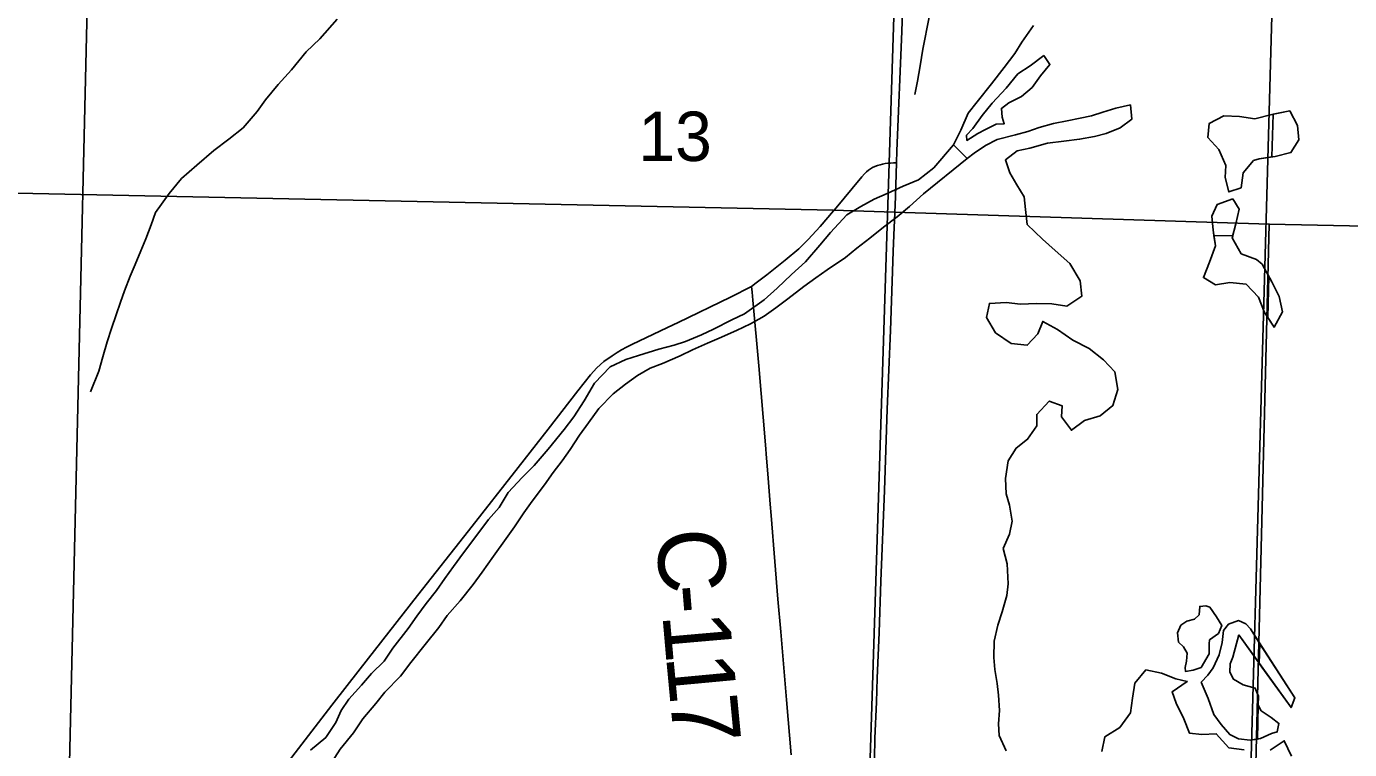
# Model space of a CAD drawing. Extents: x -38.1 to 35.9, y -2.7 to 28.5.
# Drawn here: x 20.979 to 22.099, y 18.084 to 18.696 of the extents above; entities that cross this region are included whole.
import ezdxf

# ---------------------------------------------------------------- set-up
doc = ezdxf.new("R2010")
doc.units = 0
for name, color, linetype in [('GM_X_City_Street_Text', 7, 'Continuous'), ('GM_X_Corporation', 7, 'Continuous'), ('GM_X_Interchange_Ramps', 7, 'Continuous'), ('GM_X_Interstate_Shield', 7, 'Continuous'), ('GM_X_Major_River', 7, 'Continuous'), ('GM_X_Minor_River', 7, 'Continuous'), ('GM_X_Section', 7, 'Continuous'), ('GM_X_Township', 7, 'Continuous'), ('GM_X_US_Route', 7, 'Continuous')]:
    doc.layers.add(name, color=color, linetype=linetype)

msp = doc.modelspace()

# ---------------------------------------------------------------- linework, layer by layer
at = {"layer": 'GM_X_City_Street_Text'}
for points in [[(21.6623, 18.5402), (21.663, 18.541), (21.6863, 18.569), (21.6884, 18.5713), (21.6902, 18.5731), (21.692, 18.5745), (21.6936, 18.5756), (21.6954, 18.5767), (21.6973, 18.5776), (21.6996, 18.5785), (21.7019, 18.5792), (21.7038, 18.5797), (21.706, 18.5801), (21.7082, 18.5804), (21.7105, 18.5806), (21.713, 18.5808), (21.7156, 18.5808)], [(21.5928, 18.476), (21.5968, 18.4791), (21.6058, 18.4858), (21.6214, 18.4982), (21.6328, 18.508), (21.6409, 18.5157), (21.6511, 18.5267), (21.6623, 18.5402)], [(21.5217, 18.4412), (21.5308, 18.4456), (21.575, 18.467), (21.5928, 18.476)], [(21.6056, 18.3306), (21.6046, 18.3419), (21.599, 18.4088), (21.5941, 18.4645), (21.5935, 18.4713), (21.5928, 18.476)], [(21.1781, 18.0447), (21.1847, 18.0529), (21.2178, 18.0958), (21.2376, 18.1213), (21.2615, 18.1522), (21.3101, 18.2144), (21.3532, 18.2691), (21.3954, 18.3228), (21.4206, 18.3552), (21.4457, 18.3876), (21.4565, 18.4012), (21.462, 18.4071), (21.4679, 18.4124), (21.4749, 18.4174), (21.4791, 18.42), (21.4828, 18.4223), (21.4871, 18.4246), (21.4915, 18.4269), (21.5217, 18.4412)], [(21.6087, 18.2917), (21.6067, 18.3172), (21.6056, 18.3306)], [(21.6127, 18.2431), (21.6095, 18.2819), (21.6087, 18.2917)], [(21.6264, 18.0794), (21.6226, 18.1259), (21.6178, 18.1834), (21.6152, 18.2113), (21.6127, 18.2431)]]:
    msp.add_lwpolyline(points, dxfattribs=at)
at = {"layer": 'GM_X_Corporation'}
msp.add_lwpolyline([(25.4101, 13.4873), (25.0847, 13.9186), (24.5478, 14.5412), (23.9622, 15.2897), (23.3945, 15.9977), (22.8429, 16.6968), (22.7771, 16.7664), (22.2793, 17.0387), (22.174, 17.095), (22.1183, 17.1348), (22.0806, 17.1798), (21.9636, 17.4041), (21.7841, 17.7749), (21.744, 17.8537), (21.7155, 17.9287), (21.6978, 17.9866), (21.6921, 18.0413), (21.6956, 18.1468), (21.7163, 18.7934), (21.7602, 19.7303), (21.7602, 19.7308)], dxfattribs=at)
at = {"layer": 'GM_X_Interchange_Ramps'}
msp.add_line((21.7134, 18.5196), (21.7141, 18.5385), dxfattribs=at)
for points in [[(21.7156, 18.5808), (21.7159, 18.5908), (21.72, 18.692), (21.7218, 18.7436), (21.7237, 18.7933)], [(21.7141, 18.5385), (21.7147, 18.5523), (21.7156, 18.5808)], [(21.6969, 18.076), (21.6974, 18.0934), (21.6986, 18.1238), (21.6993, 18.1443), (21.7008, 18.1828), (21.7023, 18.2263), (21.7054, 18.3032), (21.7078, 18.3722), (21.7104, 18.4386), (21.7129, 18.5057), (21.7134, 18.5196)]]:
    msp.add_lwpolyline(points, dxfattribs=at)
at = {"layer": 'GM_X_Interstate_Shield'}
for p, q in [((22.0335, 18.5857), (22.0345, 18.6219)), ((21.764, 18.5961), (21.7753, 18.5843)), ((22.0003, 18.5189), (21.9844, 18.5193)), ((22.03, 18.4497), (22.0309, 18.4845)), ((22.0228, 18.1567), (22.0233, 18.1734)), ((22.0228, 18.1567), (22.0233, 18.1734)), ((22.0219, 18.1214), (22.0221, 18.129)), ((22.0219, 18.1214), (22.0212, 18.0927))]:
    msp.add_line(p, q, dxfattribs=at)
for points in [[(21.8317, 18.6971), (21.8217, 18.683), (21.8158, 18.6733), (21.8067, 18.6614), (21.796, 18.6476), (21.7838, 18.6324), (21.7763, 18.6228), (21.7702, 18.6085), (21.764, 18.5961)], [(21.8404, 18.6718), (21.8288, 18.663), (21.8183, 18.6561), (21.8084, 18.6439), (21.7967, 18.6313), (21.788, 18.6209), (21.7801, 18.6098), (21.775, 18.6042), (21.7752, 18.5997), (21.7845, 18.6055), (21.7909, 18.609)], [(21.7909, 18.609), (21.7999, 18.6134), (21.8068, 18.6139), (21.805, 18.6193), (21.8045, 18.6269), (21.8107, 18.6317), (21.8215, 18.637), (21.8305, 18.6447), (21.8376, 18.6544), (21.8455, 18.664), (21.8404, 18.6718)], [(21.7753, 18.5843), (21.7814, 18.5889), (21.791, 18.5954), (21.8007, 18.6004), (21.8164, 18.6045), (21.8267, 18.6073), (21.8363, 18.6108), (21.8486, 18.6142), (21.86, 18.6162), (21.8711, 18.6185), (21.8807, 18.6205), (21.8903, 18.6237), (21.9014, 18.6271), (21.9136, 18.6298), (21.9148, 18.6177), (21.9051, 18.6103), (21.8931, 18.6057), (21.8832, 18.603), (21.8706, 18.6007), (21.8572, 18.5992), (21.8435, 18.5973), (21.8286, 18.5932)], [(22.0345, 18.6219), (22.0189, 18.6181), (22.006, 18.62), (21.9927, 18.6207), (21.9804, 18.6142), (21.9793, 18.6021), (21.9885, 18.592), (21.9945, 18.5785), (21.9938, 18.5683), (21.9969, 18.5561), (22.0073, 18.5596), (22.0092, 18.5724), (22.0178, 18.5828)], [(22.0323, 18.6215), (22.0189, 18.6181), (22.006, 18.62), (21.9927, 18.6207), (21.9804, 18.6142), (21.9793, 18.6021), (21.9885, 18.592), (21.9945, 18.5785), (21.9938, 18.5683), (21.9969, 18.5561), (22.0073, 18.5596), (22.0092, 18.5724), (22.0178, 18.5828)], [(22.0178, 18.5828), (22.0228, 18.5842), (22.0361, 18.5861), (22.0495, 18.5895), (22.0563, 18.6003), (22.0552, 18.6125), (22.0487, 18.6248)], [(22.0323, 18.6215), (22.0487, 18.6248)], [(22.0487, 18.6248), (22.0552, 18.6125), (22.0563, 18.6003), (22.0495, 18.5895), (22.0361, 18.5861), (22.0335, 18.5857)], [(22.0345, 18.6219), (22.0487, 18.6248)], [(21.8286, 18.5932), (21.8179, 18.5908), (21.8078, 18.5832), (21.8116, 18.5724), (21.8174, 18.562), (21.8236, 18.552), (21.8248, 18.5413), (21.8263, 18.5284), (21.8392, 18.5162), (21.8499, 18.5064), (21.8625, 18.4954), (21.8712, 18.4808), (21.8724, 18.4678), (21.8599, 18.4594), (21.8471, 18.4613), (21.8342, 18.4617), (21.8205, 18.461), (21.8084, 18.4625), (21.7943, 18.4617), (21.7917, 18.4497), (21.7993, 18.4369), (21.8127, 18.4278), (21.8263, 18.4263), (21.8353, 18.4359), (21.8394, 18.4464), (21.8518, 18.4396), (21.8648, 18.4305), (21.8786, 18.4236), (21.8909, 18.4138), (21.9005, 18.4036), (21.9031, 18.3888), (21.8989, 18.3752), (21.888, 18.3664), (21.8749, 18.3626), (21.8637, 18.3542), (21.8553, 18.3655), (21.8559, 18.3749), (21.845, 18.379), (21.8344, 18.3676), (21.8345, 18.3581), (21.8266, 18.3466), (21.8169, 18.3392), (21.8101, 18.3284), (21.8078, 18.3133), (21.8085, 18.3004), (21.8113, 18.2908), (21.8135, 18.2771), (21.8113, 18.2662), (21.806, 18.2542), (21.8094, 18.2412), (21.8101, 18.2241), (21.809, 18.2142), (21.8052, 18.2003), (21.8014, 18.189), (21.7984, 18.1755), (21.798, 18.1618), (21.7988, 18.1515), (21.8007, 18.1397), (21.8019, 18.1298), (21.8027, 18.1169), (21.802, 18.1055), (21.8025, 18.0956), (21.8085, 18.0826)], [(22.0178, 18.5828), (22.0228, 18.5842), (22.0335, 18.5857)], [(22.0004, 18.5503), (21.9871, 18.5454), (21.9826, 18.5356), (21.9838, 18.5238), (21.9857, 18.5105), (21.9807, 18.4966), (21.9754, 18.4835), (21.9858, 18.4775), (21.9977, 18.4794), (22.0117, 18.4779), (22.022, 18.4669), (22.0273, 18.4539), (22.0353, 18.4415), (22.0425, 18.4546), (22.0395, 18.4676), (22.0334, 18.4799), (22.0251, 18.4949)], [(22.0004, 18.5503), (21.9871, 18.5454), (21.9826, 18.5356), (21.9838, 18.5238), (21.9844, 18.5193)], [(22.0251, 18.4949), (22.0203, 18.4989), (22.0075, 18.5038), (21.9999, 18.5173), (22.0029, 18.529), (22.0056, 18.5414)], [(22.0003, 18.5189), (22.0029, 18.529), (22.0056, 18.5414)], [(22.0056, 18.5414), (22.0004, 18.5503)], [(21.9844, 18.5193), (21.9857, 18.5105), (21.9807, 18.4966), (21.9754, 18.4835), (21.9858, 18.4775), (21.9977, 18.4794), (22.0117, 18.4779), (22.022, 18.4669), (22.0273, 18.4539), (22.03, 18.4497)], [(22.0251, 18.4949), (22.0203, 18.4989), (22.0075, 18.5038), (21.9999, 18.5173), (22.0003, 18.5189)], [(22.0309, 18.4845), (22.0251, 18.4949)], [(22.0309, 18.4845), (22.0334, 18.4799), (22.0395, 18.4676), (22.0425, 18.4546), (22.0353, 18.4415), (22.03, 18.4497)], [(21.9866, 18.1962), (21.9808, 18.2044), (21.9774, 18.2056), (21.9724, 18.205), (21.9718, 18.1978), (21.9679, 18.1941), (21.9614, 18.1924), (21.9564, 18.1891), (21.9535, 18.1827), (21.9545, 18.1748), (21.9585, 18.1708), (21.9618, 18.1654), (21.9612, 18.1586), (21.9599, 18.1533), (21.9602, 18.1499), (21.9667, 18.1509), (21.9736, 18.1533)], [(21.9736, 18.1533), (21.9804, 18.1649), (21.9802, 18.1733), (21.9807, 18.1767), (21.9881, 18.1821), (21.991, 18.1889), (21.9866, 18.1962)], [(22.0233, 18.1734), (22.0152, 18.1859), (22.0115, 18.1902), (22.0051, 18.193), (21.9967, 18.1899), (21.9924, 18.1847), (21.9913, 18.1745), (21.9887, 18.1639), (21.9838, 18.153), (21.9791, 18.1467), (21.9736, 18.1408)], [(22.0055, 18.1809), (22.0497, 18.1193), (22.053, 18.1275), (22.0152, 18.1859), (22.0115, 18.1902), (22.0051, 18.193), (21.9967, 18.1899), (21.9924, 18.1847), (21.9913, 18.1745), (21.9887, 18.1639), (21.9838, 18.153), (21.9791, 18.1467), (21.9736, 18.1408)], [(21.9736, 18.1408), (21.9796, 18.127), (21.9842, 18.1136), (21.9904, 18.105), (21.9977, 18.0965), (22.0052, 18.0928), (22.0151, 18.0918), (22.0238, 18.0931), (22.0331, 18.0974), (22.038, 18.0987), (22.0394, 18.1059), (22.0327, 18.111), (22.0245, 18.1166), (22.0216, 18.122), (22.0222, 18.1288), (22.0194, 18.1357), (22.0092, 18.1386), (22.001, 18.1434), (21.9978, 18.1492), (21.998, 18.1564), (22.0004, 18.162), (22.0055, 18.1809)], [(22.0221, 18.129), (22.0194, 18.1357), (22.0092, 18.1386), (22.001, 18.1434), (21.9978, 18.1492), (21.998, 18.1564), (22.0004, 18.162), (22.0055, 18.1809)], [(22.0055, 18.1809), (22.0225, 18.1572)], [(22.0233, 18.1734), (22.053, 18.1275), (22.0497, 18.1193), (22.0228, 18.1567)], [(21.8894, 18.0821), (21.8921, 18.0946), (21.9048, 18.1026), (21.9136, 18.1148), (21.9154, 18.1273), (21.9173, 18.1401), (21.9268, 18.1513), (21.94, 18.1486), (21.952, 18.1437), (21.9618, 18.1415), (21.949, 18.1328), (21.9525, 18.1232), (21.959, 18.1097), (21.9636, 18.0978), (21.9742, 18.0964), (21.9863, 18.0972), (21.997, 18.0851), (22.0099, 18.0836)], [(21.9736, 18.1408), (21.9796, 18.127), (21.9842, 18.1136), (21.9904, 18.105), (21.9977, 18.0965), (22.0052, 18.0928), (22.0151, 18.0918), (22.0212, 18.0927)], [(22.0212, 18.0927), (22.0238, 18.0931), (22.0331, 18.0974), (22.038, 18.0987), (22.0394, 18.1059), (22.0327, 18.111), (22.0245, 18.1166), (22.0219, 18.1214)], [(22.0319, 18.0833), (22.0439, 18.0913), (22.05, 18.0783)]]:
    msp.add_lwpolyline(points, dxfattribs=at)
at = {"layer": 'GM_X_Major_River'}
msp.add_line((21.7134, 18.5196), (21.7141, 18.5385), dxfattribs=at)
for points in [[(21.7156, 18.5808), (21.7159, 18.5908), (21.72, 18.692), (21.7218, 18.7436), (21.7237, 18.7933)], [(21.7141, 18.5385), (21.7147, 18.5523), (21.7156, 18.5808)], [(21.6969, 18.076), (21.6974, 18.0934), (21.6986, 18.1238), (21.6993, 18.1443), (21.7008, 18.1828), (21.7023, 18.2263), (21.7054, 18.3032), (21.7078, 18.3722), (21.7104, 18.4386), (21.7129, 18.5057), (21.7134, 18.5196)]]:
    msp.add_lwpolyline(points, dxfattribs=at)
at = {"layer": 'GM_X_Section'}
msp.add_line((21.7753, 18.5843), (21.764, 18.5961), dxfattribs=at)
for points in [[(21.2419, 18.7024), (21.2274, 18.6858), (21.2157, 18.6747), (21.2034, 18.6595), (21.1921, 18.647), (21.1814, 18.634), (21.1743, 18.6243), (21.1625, 18.6103)], [(21.7434, 18.7042), (21.738, 18.677), (21.7357, 18.663), (21.7334, 18.6498), (21.7312, 18.6385)], [(21.1625, 18.6103), (21.1504, 18.6007), (21.1376, 18.5912), (21.1232, 18.5788), (21.1103, 18.5674), (21.0997, 18.5548), (21.0882, 18.5388), (21.0845, 18.5283), (21.0799, 18.5163), (21.0758, 18.5061), (21.0709, 18.4945), (21.0668, 18.4848), (21.0619, 18.4724), (21.0586, 18.4626), (21.0549, 18.4521), (21.0511, 18.4405), (21.0474, 18.4292), (21.0436, 18.4164), (21.0402, 18.4043), (21.0332, 18.3867)], [(21.764, 18.5961), (21.7472, 18.5766), (21.7343, 18.5663), (21.7213, 18.561), (21.7078, 18.5549), (21.6966, 18.5499), (21.6854, 18.5438), (21.6735, 18.5366), (21.6597, 18.5218), (21.6507, 18.511), (21.6385, 18.497), (21.6268, 18.4863), (21.6146, 18.4745), (21.6037, 18.4646), (21.587, 18.4529), (21.5762, 18.4479), (21.5608, 18.44), (21.5504, 18.435), (21.537, 18.4293), (21.5274, 18.4262), (21.5144, 18.4228), (21.4971, 18.4176), (21.4864, 18.4141), (21.4733, 18.408), (21.4599, 18.394), (21.4511, 18.3791), (21.4424, 18.3657), (21.4341, 18.3549), (21.4207, 18.3382), (21.4089, 18.3245), (21.3987, 18.3142), (21.3869, 18.3016), (21.3793, 18.2889), (21.3703, 18.2786), (21.3628, 18.2689), (21.349, 18.2504), (21.3406, 18.2388), (21.3331, 18.2288), (21.326, 18.2184), (21.3173, 18.2076), (21.3094, 18.1969), (21.3022, 18.1864), (21.2892, 18.1698), (21.2817, 18.1586), (21.2711, 18.1483), (21.2625, 18.1383), (21.2518, 18.1264), (21.2455, 18.1168), (21.241, 18.1066), (21.2323, 18.094), (21.2194, 18.0834)], [(21.4001, 18.2842), (21.4072, 18.2942), (21.4175, 18.3079), (21.425, 18.3184), (21.4326, 18.3284), (21.4393, 18.338), (21.4472, 18.35), (21.4548, 18.3604), (21.4635, 18.3726), (21.4756, 18.3852), (21.4861, 18.3932), (21.4962, 18.4005), (21.507, 18.4067), (21.5174, 18.4109), (21.5324, 18.4173), (21.5428, 18.4223), (21.5555, 18.428), (21.5655, 18.4323), (21.5802, 18.4387), (21.5921, 18.4444), (21.6037, 18.4509), (21.6134, 18.4578), (21.6235, 18.4655), (21.6371, 18.4761), (21.6472, 18.4834), (21.6569, 18.49), (21.6724, 18.5005), (21.6821, 18.5086), (21.693, 18.517), (21.7047, 18.5262), (21.7163, 18.5349), (21.7265, 18.5438), (21.7386, 18.5544), (21.7753, 18.5843)], [(21.2374, 18.073), (21.2445, 18.0842), (21.2559, 18.0979), (21.2639, 18.1098), (21.2749, 18.1227), (21.2824, 18.1324), (21.2957, 18.146), (21.3044, 18.1575), (21.3166, 18.1727), (21.3281, 18.1872), (21.3352, 18.1973), (21.3462, 18.2098), (21.3573, 18.2236), (21.3648, 18.234), (21.3743, 18.2477), (21.385, 18.2626), (21.3921, 18.2723), (21.4001, 18.2842)]]:
    msp.add_lwpolyline(points, dxfattribs=at)
at = {"layer": 'GM_X_US_Route'}
for points in [[(20.0353, 19.0758), (21.0384, 19.0503), (21.0147, 18.0482), (20.0086, 18.0758)], [(21.0384, 19.0503), (22.0424, 19.0296), (22.0145, 18.0265), (21.0147, 18.0482)], [(23.1004, 19.0039), (23.0833, 18.0071), (22.0145, 18.0265), (22.0424, 19.0296)]]:
    msp.add_lwpolyline(points, close=True, dxfattribs=at)
for points in [[(21.9943, 17.03), (21.7582, 17.2984), (21.9963, 17.2757), (22.0014, 17.3284), (22.0312, 18.5289), (21.7139, 18.539), (21.6621, 18.5408), (20.0221, 18.5749), (20.0225, 18.5923), (20.0232, 18.6265), (20.0252, 18.6991)], [(20.0252, 18.6991), (20.0232, 18.6265), (20.0225, 18.5923), (20.0221, 18.5749), (21.6621, 18.5408), (21.7139, 18.539), (22.0312, 18.5289), (25.4101, 18.4589)], [(25.4101, 18.4589), (22.0312, 18.5289), (22.0014, 17.3284), (21.9963, 17.2757), (21.7582, 17.2984), (21.9943, 17.03)]]:
    msp.add_lwpolyline(points, dxfattribs=at)

# ---------------------------------------------------------------- texts
at = {"layer": 'GM_X_Minor_River'}
msp.add_text('13', height=0.04186, rotation=0, dxfattribs=at).set_placement((21.497, 18.5823))
at = {"layer": 'GM_X_Township'}
for s, rotation, p in [('C', 273.9374, (21.5121, 18.2693)), ('-', 274.6249, (21.5154, 18.222)), ('1', 274.9816, (21.5173, 18.1983)), ('1', 275.3523, (21.5204, 18.1631)), ('7', 275.4612, (21.5237, 18.1281))]:
    msp.add_text(s, height=0.0568, rotation=rotation, dxfattribs=at).set_placement(p)

doc.saveas('drawing.dxf')
